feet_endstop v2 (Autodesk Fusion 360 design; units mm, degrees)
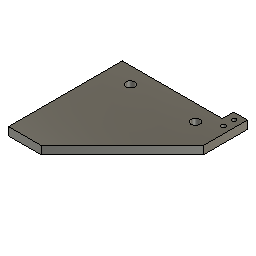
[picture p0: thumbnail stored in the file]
sketch "Sketch1" plane through (0, 0, 0) normal (0, 0, 1) x axis (1, 0, 0)
  line L1 (35, 10) -> (-35, 10)
  line L2 (35, -10) -> (35, 10)
  line L3 (-15, -60) -> (35, -10)
  line L4 (-35, -60) -> (-15, -60)
  line L5 (-35, 10) -> (-35, -60)
  point P7 (35, 0)
  point P8 (0, 10)
  point P1 (0, 0)
  point P3 (35, -10)
  point P4 (-15, -60)
  point P2 (35, 10)
  point P5 (-35, -60)
  horizontal L1
  perpendicular L1 L2
  perpendicular L2 L4
  perpendicular L4 L5
  midpoint L2 P7
  midpoint L1 P8
  vertical P1 P8
  horizontal P1 P7
  dimension "d2" distance P3 P4 = 50
  dimension "d3" distance P2 P3 = 20
  dimension "d4" angle L3 L4 = 45
  dimension "d5" distance P4 P5 = 20
extrude "Extrude1" new body sketch "Sketch1" along normal blind 5
sketch "Sketch2" plane through (0, 0, 5) normal (0, 0, 1) x axis (-1, 0, 0)
  line L1 (15, 60) -> (35, 60)
  line L2 (-35, 10) -> (15, 60)
  line L3 (-35, -10) -> (-35, 10)
  line L4 (35, -10) -> (-35, -10)
  line L5 (35, 60) -> (35, -10)
  circle C1 centre (-20, 0) radius 2.7
  circle C2 centre (20, 0) radius 2.7
  point P1 (0, 0)
  point P8 (20, 0)
  point P7 (-20, 0)
  horizontal P1 P8
  horizontal P1 P7
  dimension "d8" diameter C1 = 5.4
  dimension "d9" diameter C2 = 5.4
  dimension "d10" distance P1 P8 = 20
  dimension "d11" distance P1 P7 = 20
extrude "Extrude2" cut sketch "Sketch2" profile of C1 C2 against normal blind 10
sketch "Sketch3" plane through (0, 0, 5) normal (0, 0, 1) x axis (-1, 0, 0)
  line L1 (15, 60) -> (35, 60)
  line L2 (-35, 10) -> (15, 60)
  line L3 (-35, -10) -> (-35, 10)
  line L4 (35, -10) -> (-35, -10)
  line L5 (35, 60) -> (35, -10)
  circle C1 centre (20, 0) radius 2.7
  circle C2 centre (-20, 0) radius 2.7
sketch "Sketch4" plane through (0, 0, 5) normal (0, 0, 1) x axis (-1, 0, 0)
  line L1 (15, 60) -> (35, 60)
  line L2 (-35, 10) -> (15, 60)
  line L3 (-35, -10) -> (-35, 10)
  line L4 (35, -10) -> (-35, -10)
  line L5 (35, 60) -> (35, -10)
  line L6 (-26.5, -10) -> (-35, -10)
  line L7 (-26.5, -17) -> (-26.5, -10)
  line L8 (-35, -17) -> (-26.5, -17)
  line L9 (-35, -10) -> (-35, -17)
  circle C1 centre (20, 0) radius 2.7
  circle C2 centre (-20, 0) radius 2.7
  point P7 (-35, -10)
  point P9 (-35, -10)
  point P10 (-26.5, -10)
  point P12 (-35, -17)
  horizontal L6
  vertical L7
  horizontal L8
  vertical L9
  coincident P7 P9
  dimension "d14" distance P9 P10 = 8.5
  dimension "d15" distance P9 P12 = 7
extrude "Extrude3" add sketch "Sketch4" profile of L4 L6 L7 L8 L9 to an object
sketch "Sketch6" plane through (0, 0, 5) normal (0, 0, 1) x axis (-1, 0, 0)
  line L1 (15, 60) -> (35, 60)
  line L2 (-35, 10) -> (15, 60)
  line L3 (-35, -17) -> (-35, 10)
  line L4 (-26.5, -17) -> (-35, -17)
  line L5 (-26.5, -10) -> (-26.5, -17)
  line L6 (35, -10) -> (-26.5, -10)
  line L7 (35, 60) -> (35, -10)
  circle C1 centre (20, 0) radius 2.7
  circle C2 centre (-20, 0) radius 2.7
  circle C3 centre (-30.75, -13) radius 1.25
  circle C4 centre (-30.75, -6.5) radius 1.25
  point P11 (-30.75, -13)
  point P12 (-30.75, -6.5)
  point P13 (-30.75, -17)
  vertical P11 P12
  midpoint L4 P13
  vertical P11 P13
  dimension "d18" diameter C3 = 2.5
  dimension "d19" diameter C4 = 2.5
  dimension "d20" distance P11 P12 = 6.5
  dimension "d21" distance P11 P13 = 4
extrude "Extrude4" cut sketch "Sketch6" profile of C3 C4 against normal blind 8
